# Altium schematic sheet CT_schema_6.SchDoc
size 293 x 258 mm
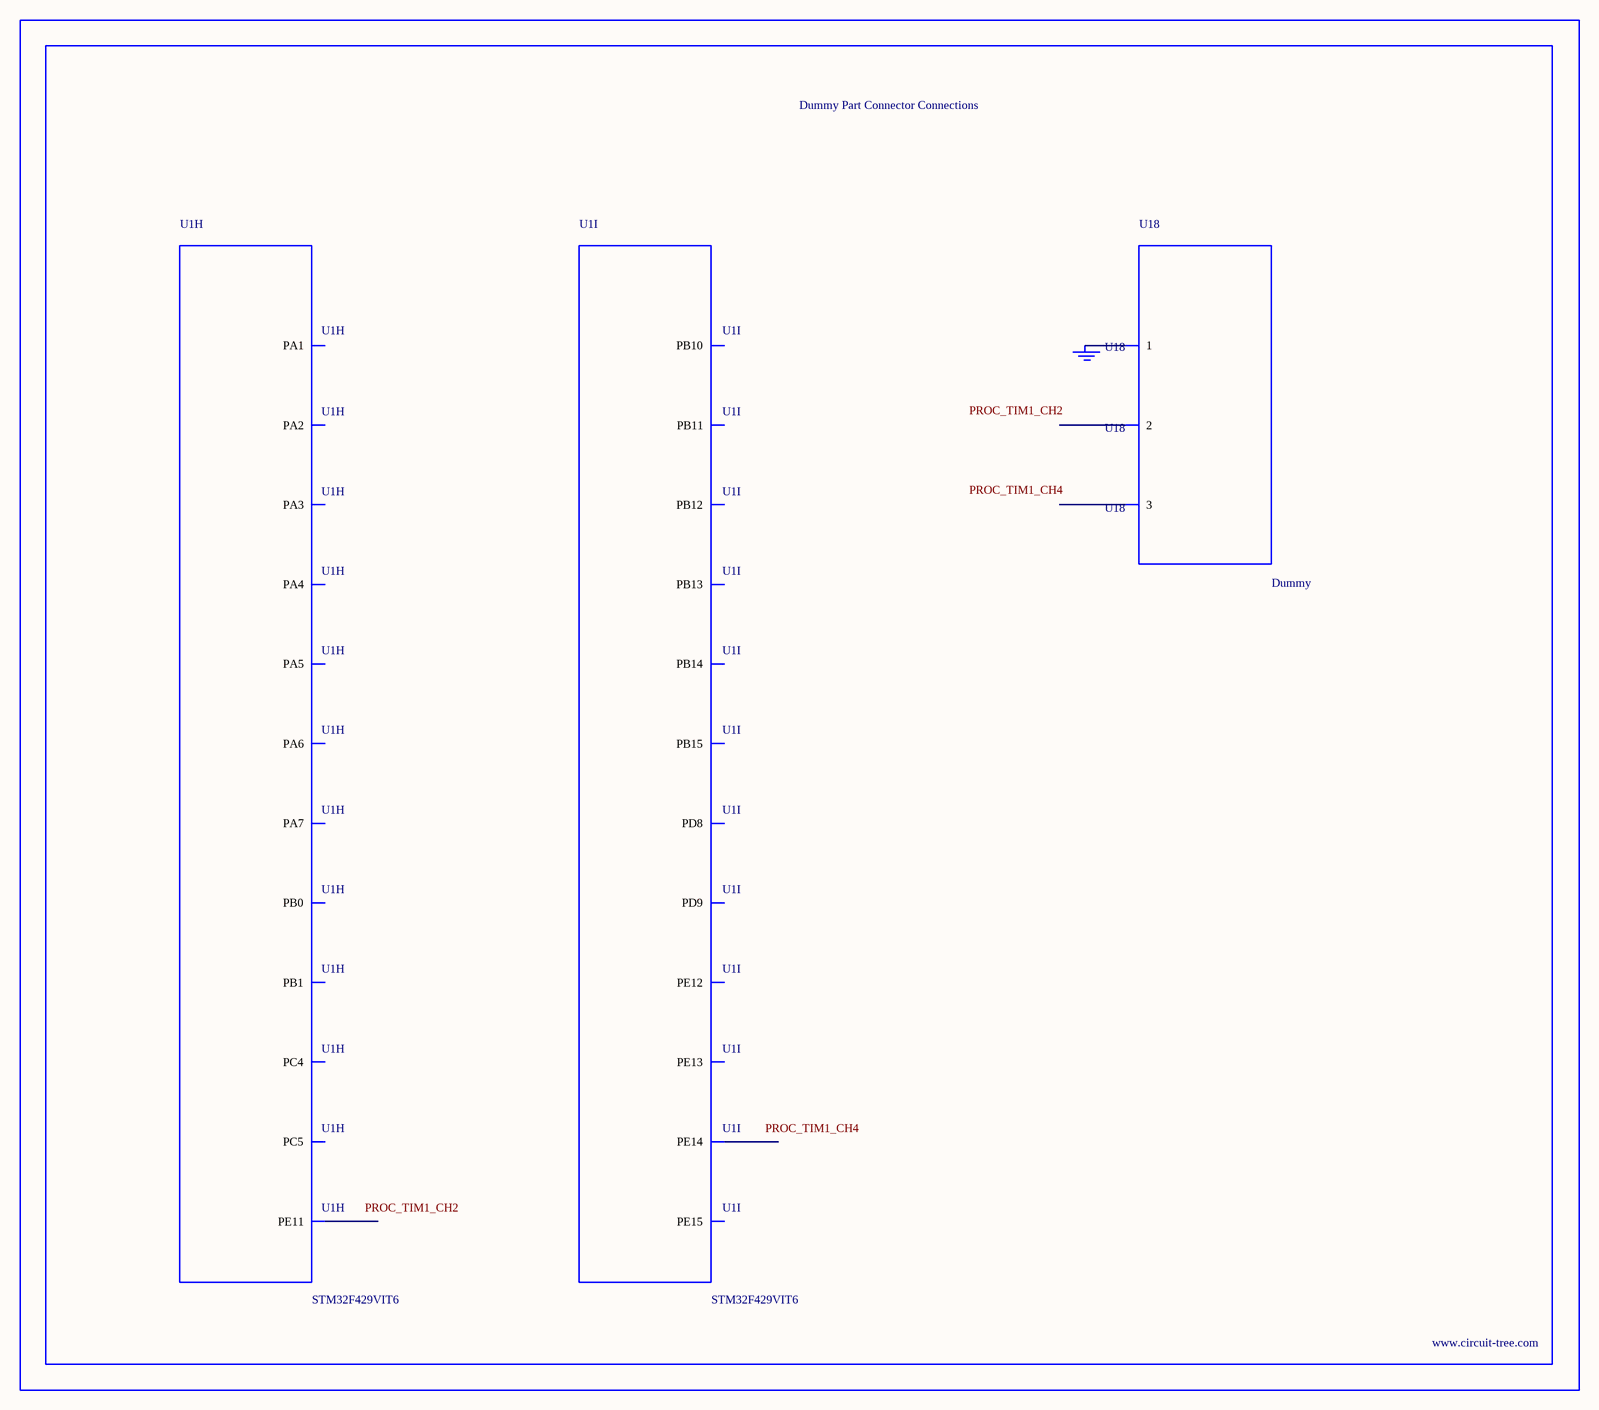
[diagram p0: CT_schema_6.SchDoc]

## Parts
BORDER5  (no value)
GND_INSTANCE_5_0  (no value)
U1  STM32F429VIT6  [LQFP100]  (parts H,I of 9)
U18  Dummy  [DUMMY_PACKAGE_174]

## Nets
NetGND_INSTANCE_5_0_0: GND_INSTANCE_5_0.0(GND) U18.1

Not connected (* = marked no-connect by the designer): U1 24(PA1) 25(PA2) 26(PA3) 29(PA4) 30(PA5) 31(PA6) 32(PA7) 33(PC4) 34(PC5) 35(PB0) 36(PB1) 42(PE11) 43(PE12) 44(PE13) 45(PE14) 46(PE15) 47(PB10) 48(PB11) 51(PB12) 52(PB13) 53(PB14) 54(PB15) 55(PD8) 56(PD9); U18 2 3

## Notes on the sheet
- Labels drawn without touching a wire or pin: PROC_TIM1_CH2, PROC_TIM1_CH4

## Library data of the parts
BORDER5 = BORDER_PAGE5
GND_INSTANCE_5_0 = GND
